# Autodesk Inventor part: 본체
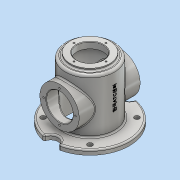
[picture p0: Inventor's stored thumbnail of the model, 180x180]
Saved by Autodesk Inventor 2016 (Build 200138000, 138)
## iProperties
Created: 2018-04
Part Number: 본체
Material: 알루미늄 6061
Document SubType Name: Modeling
Designer: Administrator
Density: 2.7 g/cm^3
Appearance: 알루미늄 - 평지
Mass: 1147.05 g
Surface Area: 1200.37 cm^2
Volume: 424.834 cm^3
Author: Administrator
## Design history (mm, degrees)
sketch "스케치1"
  geometry: C1 r 80 at (0, 0); 1 further point
  constraints: 1 centre point, 1 coincident
  dimensions: "d0" = 160 diameter of C1
extrude "돌출1" new body sketch "스케치1" distance "d1" = 10; taper "d2" = 0 deg
sketch "스케치2"
  geometry: C1 r 50 at (0, 0); 1 further point
  constraints: 1 centre point, 1 coincident
  dimensions: "d3" = 100 diameter of C1
extrude "돌출2" join sketch "스케치2" distance "d4" = 8; taper "d5" = 0 deg
sketch "스케치3"
  geometry: C1 r 50 at (0, 0); 1 further point
  constraints: 1 centre point, 1 coincident
  dimensions: "d6" = 100 diameter of C1
extrude "돌출3" join sketch "스케치3" distance "d7" = 110; taper "d8" = 0 deg
sketch "스케치4"
  geometry: C1 r 40 at (0, 0); 1 further point
  constraints: 1 centre point, 1 coincident
  dimensions: "d9" = 80 diameter of C1
extrude "돌출4" join sketch "스케치4" distance "d10" = 5; taper "d11" = 0 deg
sketch "스케치5"
  geometry: C1 r 45 at (0, 0); 1 further point
  constraints: 1 centre point, 1 coincident
  dimensions: "d12" = 90 diameter of C1
extrude "돌출5" cut sketch "스케치5" distance "d13" = 120; taper "d14" = 0 deg
node "작업 평면2"
sketch "스케치6"
  geometry: L1 (-80, 0)-(80, 0) reference; C1 r 40 at (0, 60); 2 further points
  constraints: 1 centre point, 1 midpoint, 1 vertical alignment
  dimensions: "d17" = 80 diameter of C1; "d18" = 60 distance from line of L1 C1.centre
extrude "돌출6" join sketch "스케치6" stored distance "d19" = 120; taper "d20" = 0 deg
sketch "스케치7"
  geometry: C1 r 40 at (0, 0) reference; C2 r 27 at (0, 0); 1 further point
  constraints: 1 centre point, 1 coincident
  dimensions: "d21" = 54 diameter of C2
extrude "돌출7" cut sketch "스케치7" distance "d22" = 150; taper "d23" = 0 deg
sketch "스케치8"
  geometry: C1 r 27 at (0, 0); 1 further point
  constraints: 1 centre point, 1 coincident
  dimensions: "d24" = 54 diameter of C1
extrude "돌출8" cut sketch "스케치8" distance "d25" = 150; taper "d26" = 0 deg
sketch "스케치9"
  geometry: C1 r 50 at (0, 0) reference; C2 r 15 at (0, -80); 3 further points
  constraints: 3 vertical alignment, 1 centre point, 2 other
  dimensions: "d27" = 30 diameter of C2
extrude "돌출9" cut sketch "스케치9" distance "d28" = 150; taper "d29" = 0 deg
chamfer "모따기1" distance "d33" = 1; stored, may be unused: second distance "d34" = 2, angle "d35" = 45 deg
fillet "모깎기1" dims "d36" = 3
fillet "모깎기2" dims "d37" = 5
fillet "모깎기3" dims "d38" = 3
sketch "스케치10" dims "d39" = 65
  geometry: C1 r 45 at (0, 0) reference; 3 further points
  constraints: 2 vertical alignment, 1 coincident, 2 other
hole "구멍1" sketch "스케치10" at (0, 32.5) diameter "d40" = 3.242; stored, may be unused: countersink angle "d44" = 90 deg, drill point angle "d46" = 118 deg; dims "d41" = 8, "d42" = 4, "d43" = 2, "d45" = 10
sketch "스케치11" dims "d50" = 65
  geometry: C1 r 40 at (0, 0) reference; C2 r 28 at (0, 0) reference; 3 further points
  constraints: 2 vertical alignment, 1 coincident, 2 other
hole "구멍2" sketch "스케치11" at (0, 32.5) diameter "d51" = 3.242; stored, may be unused: countersink angle "d55" = 90 deg, drill point angle "d57" = 118 deg; dims "d52" = 8, "d53" = 4, "d54" = 2, "d56" = 10
sketch "스케치12" dims "d61" = 135
  geometry: L1 (0, 0)-(-73.648, -73.648); L2 (-112, 0)-(112, 0) reference; 2 further points
  constraints: 2 end point, 1 coincident, 1 point on line, 3 other
  dimensions: "d62" = 45 deg angle of L2 L1
hole "구멍3" sketch "스케치12" at (-47.73, -47.73) diameter "d63" = 10; stored, may be unused: countersink angle "d67" = 90 deg, drill point angle "d69" = 118 deg; dims "d64" = 8, "d65" = 4, "d66" = 2, "d68" = 10
chamfer "모따기2" distance "d73" = 1; stored, may be unused: second distance "d74" = 2, angle "d75" = 45 deg
node "작업 평면3"
sketch "스케치13"
  geometry: L1 (-77.955, 0)-(77.955, 0) reference; 3 further points
  constraints: 1 midpoint, 1 other
  dimensions: "d80" = 70 distance from line of L1 point (0, 70)
feature "엠보싱2" sketch "스케치13" dims "d81" = 0.5, "d82" = 0
node "솔리드1"
mirror "대칭1"
pattern_circular "원형 패턴1" dims angle "d31" = 360 deg
pattern_circular "원형 패턴2" dims angle "d48" = 360 deg
pattern_circular "원형 패턴3" dims angle "d59" = 360 deg
mirror "대칭2"
pattern_circular "원형 패턴4" dims angle "d71" = 360 deg
node "투영된 루프1"
node "투영된 루프2"
node "투영된 루프3"
other parameters: "d16" = -62
